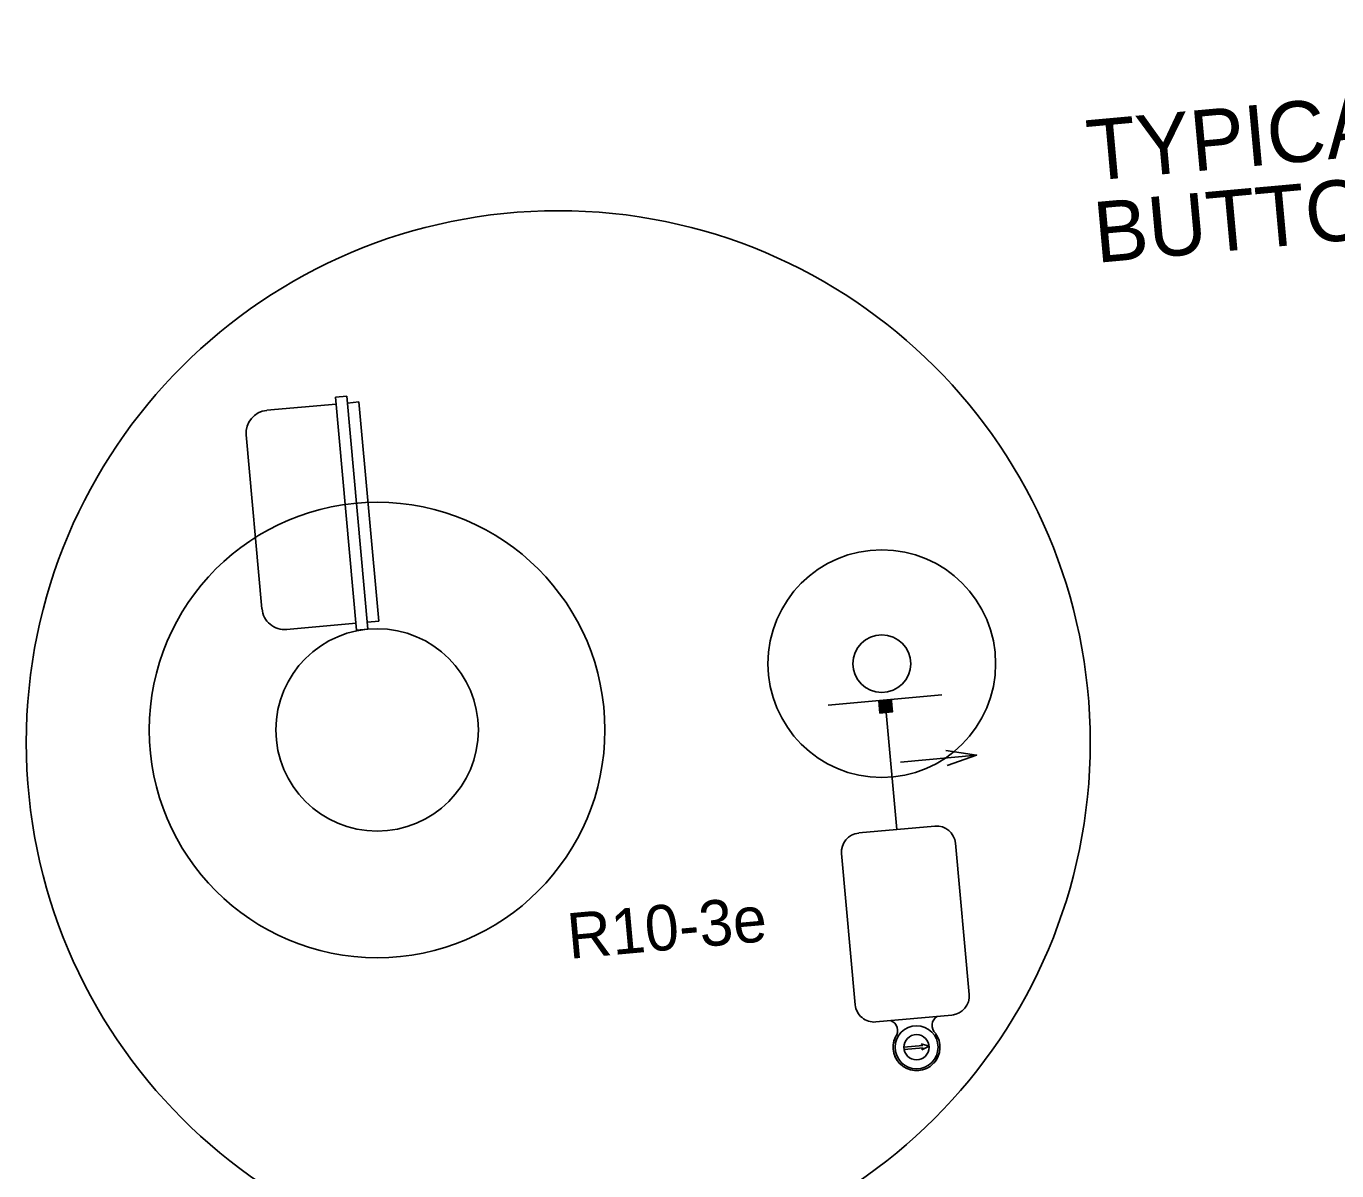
# Model space of a CAD drawing. Extents: x 1277218 to 1279252, y 196860 to 197529.
# Drawn here: x 1278874.2 to 1279006.3, y 197075.7 to 197191 of the extents above; entities that cross this region are included whole.
import ezdxf

# ---------------------------------------------------------------- set-up
doc = ezdxf.new("R2010")
doc.units = 0
doc.layers.add('R_Point Sym', color=7, linetype='Continuous')
doc.layers.add('S_EDGE_PAVEMENT', color=7, linetype='Continuous')

msp = doc.modelspace()

# ---------------------------------------------------------------- linework, layer by layer
at = {"layer": 'S_EDGE_PAVEMENT'}
for p, q in [((1278906.53, 197153.75), (1278905.39, 197153.65)), ((1278907.52, 197130.16), (1278905.39, 197153.65)), ((1278908.66, 197130.26), (1278906.53, 197153.75)), ((1278905.45, 197152.95), (1278898.47, 197152.32)), ((1278907.74, 197153.16), (1278906.6, 197153.05)), ((1278909.74, 197131.06), (1278907.74, 197153.16)), ((1278897.98, 197132.3), (1278896.39, 197149.83)), ((1278907.46, 197130.86), (1278900.47, 197130.22)), ((1278908.66, 197130.26), (1278907.52, 197130.16)), ((1278909.74, 197131.06), (1278908.6, 197130.96)), ((1278966.46, 197123.64), (1278955.03, 197122.6)), ((1278960.11, 197123.05), (1278960.12, 197123.07)), ((1278960.23, 197121.79), (1278960.11, 197123.06)), ((1278960.12, 197122.95), (1278960.23, 197123.08)), ((1278960.12, 197122.97), (1278960.21, 197123.07)), ((1278960.12, 197122.99), (1278960.19, 197123.07)), ((1278960.12, 197123.01), (1278960.17, 197123.07)), ((1278960.12, 197123.03), (1278960.15, 197123.07)), ((1278960.13, 197122.84), (1278960.34, 197123.08)), ((1278960.13, 197122.86), (1278960.32, 197123.08)), ((1278960.13, 197122.88), (1278960.3, 197123.08)), ((1278960.13, 197122.9), (1278960.28, 197123.08)), ((1278960.13, 197122.92), (1278960.25, 197123.08)), ((1278960.14, 197122.73), (1278960.45, 197123.09)), ((1278960.14, 197122.75), (1278960.43, 197123.09)), ((1278960.14, 197122.77), (1278960.4, 197123.09)), ((1278960.14, 197122.79), (1278960.38, 197123.09)), ((1278960.14, 197122.82), (1278960.36, 197123.09)), ((1278960.15, 197122.62), (1278960.56, 197123.1)), ((1278960.15, 197122.64), (1278960.53, 197123.1)), ((1278960.15, 197122.67), (1278960.51, 197123.1)), ((1278960.15, 197122.69), (1278960.49, 197123.1)), ((1278960.15, 197122.71), (1278960.47, 197123.1)), ((1278960.16, 197122.51), (1278960.66, 197123.11)), ((1278960.16, 197122.54), (1278960.64, 197123.11)), ((1278960.16, 197122.56), (1278960.62, 197123.11)), ((1278960.16, 197122.58), (1278960.6, 197123.11)), ((1278960.16, 197122.6), (1278960.58, 197123.11)), ((1278960.17, 197122.39), (1278960.79, 197123.13)), ((1278960.17, 197122.41), (1278960.77, 197123.12)), ((1278960.17, 197122.43), (1278960.75, 197123.12)), ((1278960.17, 197122.45), (1278960.73, 197123.12)), ((1278960.17, 197122.47), (1278960.71, 197123.12)), ((1278960.17, 197122.49), (1278960.68, 197123.12)), ((1278960.18, 197122.28), (1278960.9, 197123.14)), ((1278960.18, 197122.3), (1278960.88, 197123.13)), ((1278960.18, 197122.32), (1278960.86, 197123.13)), ((1278960.18, 197122.34), (1278960.84, 197123.13)), ((1278960.18, 197122.36), (1278960.81, 197123.13)), ((1278960.19, 197122.17), (1278961.01, 197123.15)), ((1278960.19, 197122.19), (1278960.99, 197123.14)), ((1278960.19, 197122.21), (1278960.96, 197123.14)), ((1278960.19, 197122.23), (1278960.94, 197123.14)), ((1278960.19, 197122.26), (1278960.92, 197123.14)), ((1278960.2, 197122.06), (1278961.12, 197123.16)), ((1278960.2, 197122.08), (1278961.09, 197123.15)), ((1278960.2, 197122.11), (1278961.07, 197123.15)), ((1278960.2, 197122.13), (1278961.05, 197123.15)), ((1278960.2, 197122.15), (1278961.03, 197123.15)), ((1278960.21, 197121.95), (1278961.22, 197123.16)), ((1278960.21, 197121.98), (1278961.2, 197123.16)), ((1278960.21, 197122), (1278961.18, 197123.16)), ((1278960.21, 197122.02), (1278961.16, 197123.16)), ((1278960.21, 197122.04), (1278961.14, 197123.16)), ((1278960.22, 197121.85), (1278961.33, 197123.17)), ((1278960.22, 197121.87), (1278961.31, 197123.17)), ((1278960.22, 197121.89), (1278961.29, 197123.17)), ((1278960.22, 197121.91), (1278961.27, 197123.17)), ((1278960.22, 197121.93), (1278961.24, 197123.17)), ((1278960.23, 197121.8), (1278961.37, 197123.18)), ((1278960.23, 197121.83), (1278961.35, 197123.18)), ((1278960.23, 197121.79), (1278961.5, 197121.91)), ((1278960.24, 197121.8), (1278961.38, 197123.17)), ((1278960.26, 197121.8), (1278961.39, 197123.15)), ((1278960.28, 197121.8), (1278961.39, 197123.12)), ((1278960.31, 197121.8), (1278961.39, 197123.1)), ((1278960.33, 197121.8), (1278961.39, 197123.08)), ((1278960.35, 197121.81), (1278961.39, 197123.06)), ((1278960.37, 197121.81), (1278961.4, 197123.04)), ((1278960.39, 197121.81), (1278961.4, 197123.02)), ((1278960.41, 197121.81), (1278961.4, 197122.99)), ((1278960.43, 197121.81), (1278961.4, 197122.97)), ((1278960.46, 197121.82), (1278961.4, 197122.95)), ((1278960.48, 197121.82), (1278961.41, 197122.93)), ((1278960.5, 197121.82), (1278961.41, 197122.91)), ((1278960.52, 197121.82), (1278961.41, 197122.89)), ((1278960.54, 197121.82), (1278961.41, 197122.87)), ((1278960.56, 197121.83), (1278961.41, 197122.84)), ((1278960.59, 197121.83), (1278961.42, 197122.82)), ((1278960.61, 197121.83), (1278961.42, 197122.8)), ((1278960.63, 197121.83), (1278961.42, 197122.78)), ((1278960.65, 197121.83), (1278961.42, 197122.76)), ((1278960.67, 197121.83), (1278961.42, 197122.74)), ((1278960.69, 197121.84), (1278961.43, 197122.71)), ((1278960.71, 197121.84), (1278961.43, 197122.69)), ((1278960.74, 197121.84), (1278961.43, 197122.67)), ((1278960.76, 197121.84), (1278961.43, 197122.65)), ((1278960.78, 197121.84), (1278961.43, 197122.63)), ((1278960.8, 197121.85), (1278961.44, 197122.61)), ((1278960.82, 197121.85), (1278961.44, 197122.59)), ((1278960.84, 197121.85), (1278961.44, 197122.56)), ((1278960.87, 197121.85), (1278961.44, 197122.54)), ((1278960.89, 197121.85), (1278961.44, 197122.52)), ((1278960.91, 197121.86), (1278961.44, 197122.5)), ((1278960.93, 197121.86), (1278961.45, 197122.48)), ((1278960.95, 197121.86), (1278961.45, 197122.46)), ((1278960.97, 197121.86), (1278961.45, 197122.43)), ((1278961, 197121.86), (1278961.45, 197122.41)), ((1278961.02, 197121.87), (1278961.45, 197122.39)), ((1278961.04, 197121.87), (1278961.46, 197122.37)), ((1278961.06, 197121.87), (1278961.46, 197122.35)), ((1278961.08, 197121.87), (1278961.46, 197122.33)), ((1278961.1, 197121.87), (1278961.46, 197122.31)), ((1278961.12, 197121.88), (1278961.46, 197122.28)), ((1278961.15, 197121.88), (1278961.47, 197122.26)), ((1278961.17, 197121.88), (1278961.47, 197122.24)), ((1278961.19, 197121.88), (1278961.47, 197122.22)), ((1278961.21, 197121.88), (1278961.47, 197122.2)), ((1278961.23, 197121.89), (1278961.47, 197122.18)), ((1278961.25, 197121.89), (1278961.48, 197122.15)), ((1278961.28, 197121.89), (1278961.48, 197122.13)), ((1278961.3, 197121.89), (1278961.48, 197122.11)), ((1278961.32, 197121.89), (1278961.48, 197122.09)), ((1278961.34, 197121.9), (1278961.48, 197122.07)), ((1278961.36, 197121.9), (1278961.49, 197122.05)), ((1278961.5, 197121.91), (1278961.38, 197123.18)), ((1278961.38, 197121.9), (1278961.49, 197122.02)), ((1278961.4, 197121.9), (1278961.49, 197122)), ((1278961.43, 197121.9), (1278961.49, 197121.98)), ((1278961.45, 197121.91), (1278961.49, 197121.96)), ((1278961.47, 197121.91), (1278961.5, 197121.94)), ((1278961.49, 197121.91), (1278961.5, 197121.92)), ((1278960.86, 197121.85), (1278961.93, 197110.06)), ((1278962.31, 197116.86), (1278969.97, 197117.56)), ((1278958.1, 197109.72), (1278965.77, 197110.41)), ((1278967.84, 197108.68), (1278969.22, 197093.44)), ((1278957.75, 197092.4), (1278956.37, 197107.64)), ((1278967.49, 197091.37), (1278959.82, 197090.67)), ((1278964.56, 197088.3), (1278962.65, 197088.12)), ((1278962.65, 197088.12), (1278962.67, 197087.89)), ((1278964.58, 197088.07), (1278962.67, 197087.89)), ((1278964.39, 197088.47), (1278965.19, 197088.24)), ((1278964.56, 197088.3), (1278964.39, 197088.47)), ((1278964.45, 197087.86), (1278965.19, 197088.24)), ((1278964.45, 197087.86), (1278964.58, 197088.07))]:
    msp.add_line(p, q, dxfattribs=at)
msp.add_lwpolyline([(1278966.86, 197118.04), (1278969.97, 197117.56), (1278967, 197116.52)], dxfattribs=at)
for centre, radius in [((1278927.83, 197118.84), 53.59), ((1278909.58, 197120.1), 22.95), ((1278960.42, 197126.78), 11.47), ((1278909.58, 197120.1), 10.2), ((1278960.42, 197126.78), 2.91), ((1278963.92, 197088.12), 2.17), ((1278963.92, 197088.12), 1.27)]:
    msp.add_circle(centre, radius, dxfattribs=at)
for centre, radius, start, end in [((1278898.68, 197150.03), 2.29, 95.1779, 185.1779), ((1278900.27, 197132.51), 2.29, 185.1779, 275.1779), ((1278965.94, 197108.51), 1.91, 5.1779, 95.1779), ((1278958.27, 197107.81), 1.91, 95.1779, 185.1779), ((1278967.32, 197093.27), 1.91, 275.1779, 5.1779), ((1278959.65, 197092.57), 1.91, 185.1779, 275.1779), ((1278960.94, 197089.8), 1.07, 323.3751, 69.9823), ((1278966.55, 197090.31), 1.07, 120.3735, 226.9807), ((1278963.92, 197088.12), 2.36, 153.9181, 36.4377), ((1278963.92, 197088.12), 2.36, 153.9181, 232.6712), ((1278963.92, 197088.12), 2.36, 317.6845, 36.4377)]:
    msp.add_arc(centre, radius, start, end, dxfattribs=at)

# ---------------------------------------------------------------- texts
at = {"layer": 'R_Point Sym'}
for s, p in [('TYPICAL MOUNTING PUSH ', (1278981.35, 197175.43)), ('BUTTON ON SIGNAL POLE ', (1278982.06, 197167.17))]:
    msp.add_text(s, height=6.1199, rotation=5.1779, dxfattribs=at).set_placement(p)
at = {"layer": 'S_EDGE_PAVEMENT'}
msp.add_text('R10-3e', height=4.59, rotation=5.1779, dxfattribs=at).set_placement((1278928.95, 197097.02))

doc.saveas('drawing.dxf')
